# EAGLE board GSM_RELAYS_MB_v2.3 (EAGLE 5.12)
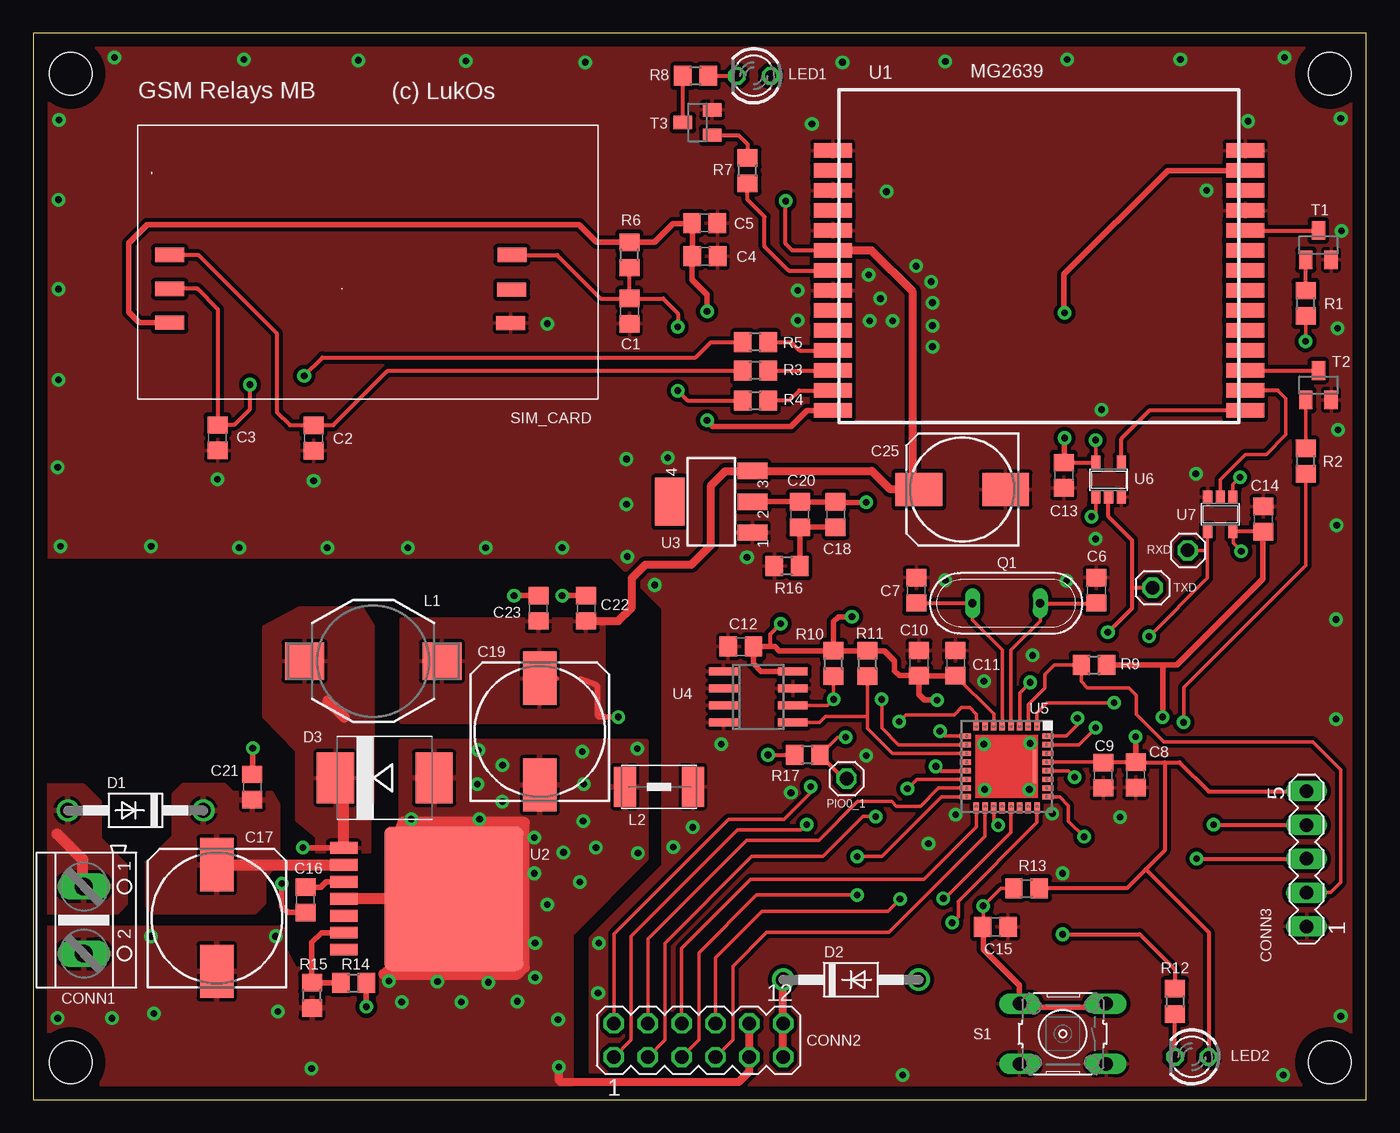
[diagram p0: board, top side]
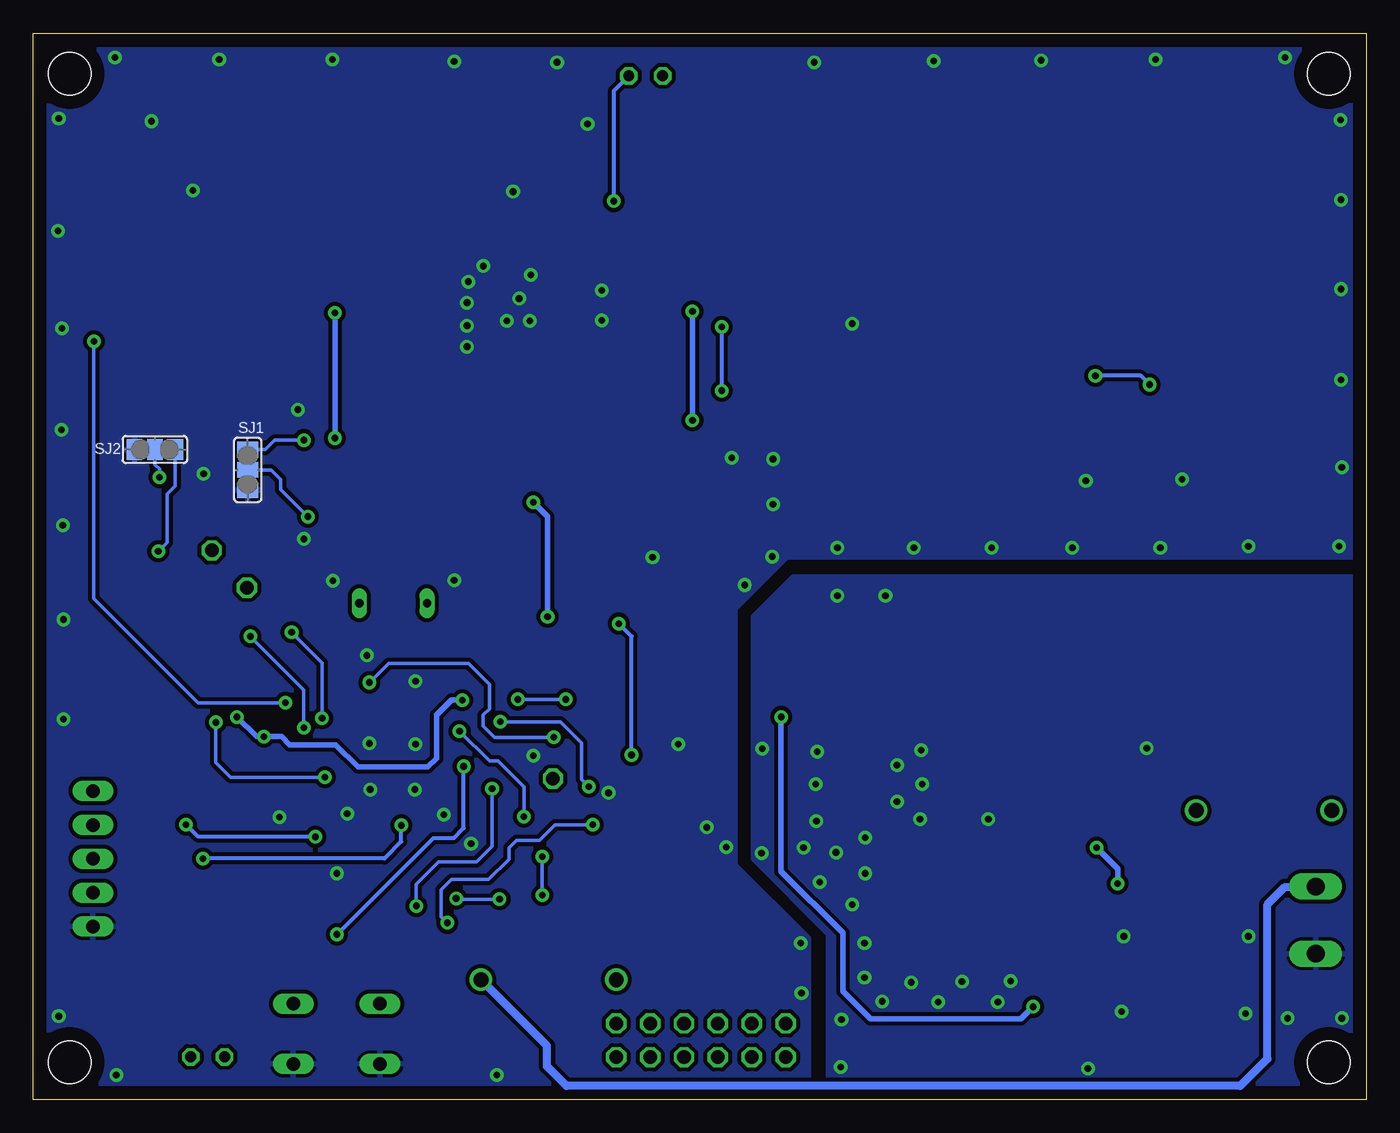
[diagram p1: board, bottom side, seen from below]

Size 100 x 80 mm. Coordinates in mm from the lower left corner, seen from the top.
Outline: 0,0 100,0 100,80 0,80 0,0
Copper layers (1*16): Top 0.035mm / dielectric 1.5mm / Bottom 0.035mm
Design rules "default": minimum track width 10mil, minimum drill 24mil, track to track 8mil, track to pad 8mil, pad to pad 8mil, via to via 8mil, smd to smd 8mil, copper to edge 40mil, drill to drill 8mil, minimum pad ring 10mil, minimum via ring 8mil, stop-mask expansion 4mil, vias tented up to drill 0mil, thermal gap 10mil
Holes 3.2 mm at 2.79,2.79 2.79,76.96 97.28,2.79 97.28,76.96
tRestrict: area 51.4,31.3 to 52.3,31.6; area 51.3,30.1 to 52.2,30.3; area 51.3,28.8 to 52.2,29.1

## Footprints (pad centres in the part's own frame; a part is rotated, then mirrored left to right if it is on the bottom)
C0805 = smd 1.3 x 1.5: 1 -0.95,0; 2 0.95,0
153CLV-1010 = smd 4 x 2.5: + 4,0; - -4,0
153CLV-0810 = smd 3.5 x 2.5: + 3.25,0; - -3.25,0
AK500/2 = drill 1.321 long: 1 -2.515,0; 2 2.515,0
MA06-2 = drill 1.016 octagon: 1 -6.35,-1.27; 2 -6.35,1.27; 3 -3.81,-1.27; 4 -3.81,1.27; 5 -1.27,-1.27; 6 -1.27,1.27; 7 1.27,-1.27; 8 1.27,1.27; 9 3.81,-1.27; 10 3.81,1.27; 11 6.35,-1.27; 12 6.35,1.27
MA05-1 = drill 1.016 long: 1 -5.08,0; 2 -2.54,0; 3 0,0; 4 2.54,0; 5 5.08,0
DO41-10 = drill 1.118 round: A 5.08,0; C -5.08,0
SMC = smd 2.8 x 3.8: A 3.7,0; C -3.7,0
P0762NL = smd 2.794 x 2.921: 1 0,5.156; 2 0,-5.156
1812 = smd 1.65 x 3: 1 -2.55,0; 2 2.55,0
LED3MM = drill 0.813 octagon: A -1.27,0; K 1.27,0
1X01 = drill 1.016 octagon: 1 0,0
QS = drill 0.61 long: 1 -2.54,0; 2 2.54,0
R0805 = smd 1.3 x 1.5: 1 -0.95,0; 2 0.95,0
B3F-10XX = drill 1.016 long: 1 -3.251,2.261; 2 3.251,2.261; 3 -3.251,-2.261; 4 3.251,-2.261
UICC_READER_I = smd 2.184 x 1.067: C1 12.88,2.54; C2 12.88,0; C3 12.88,-2.54; C5 -12.7,2.58; C6 -12.78,0.06; C7 -12.8,-2.54
SJ_2 = smd 1.168 x 1.6: 1 -1.524,0; 2 0,0; 3 1.524,0
SOT23 = smd 1 x 1.4: 1 -0.95,-1.1; 2 0.95,-1.1; 3 0,1.1
F_MG2639 = smd 1.1 x 2.85: 1 -8.724,-16.361; 2 -7.224,-16.361; 3 -5.724,-16.361; 4 -4.224,-16.361; 5 -2.724,-16.361; 6 -1.224,-16.361; 7 0.276,-16.361; 8 1.776,-16.361; 9 3.276,-16.361; 10 4.776,-16.361; 11 6.276,-16.361; 12 7.776,-16.361; 13 9.276,-16.361; 14 10.776,-16.361; 15 10.776,14.561; 16 9.276,14.561; 17 7.776,14.561; 18 6.276,14.561; 19 4.776,14.561; 20 3.276,14.561; 21 1.776,14.561; 22 0.276,14.561; 23 -1.224,14.561; 24 -2.724,14.561; 25 -4.224,14.561; 26 -5.724,14.561; 27 -7.224,14.561; 28 -8.724,14.561
TO263-7 = smd 0.91 x 2.16: 1 -3.81,-8.255; 2 -2.54,-8.255; 3 -1.27,-8.255; 4 0,-8.255; 5 1.27,-8.255; 6 2.54,-8.255; 7 3.81,-8.255 | smd 10.8 x 10.41: P$8 0,0
SOT223 = smd 1.219 x 2.235: 1 -2.311,-3.099; 2 0,-3.099; 3 2.311,-3.099 | smd 3.6 x 2.2: 4 0,3.099
SO-08 = smd 0.6 x 2.2: 1 -1.905,-2.6; 2 -0.635,-2.6; 3 0.635,-2.6; 4 1.905,-2.6; 5 1.905,2.6; 6 0.635,2.6; 7 -0.635,2.6; 8 -1.905,2.6
HVQFN33-7X7 = smd 0.813 x 0.406: 1 -3.1,2.275; 2 -3.1,1.625; 3 -3.1,0.975; 4 -3.1,0.325; 5 -3.1,-0.325; 6 -3.1,-0.975; 7 -3.1,-1.625; 8 -3.1,-2.275; 17 3.1,-2.275; 18 3.1,-1.625; 19 3.1,-0.975; 20 3.1,-0.325; 21 3.1,0.325; 22 3.1,0.975; 23 3.1,1.625; 24 3.1,2.275 | smd 0.406 x 0.813: 9 -2.275,-3.1; 10 -1.625,-3.1; 11 -0.975,-3.1; 12 -0.325,-3.1; 13 0.325,-3.1; 14 0.975,-3.1; 15 1.625,-3.1; 16 2.275,-3.1; 25 2.275,3.1; 26 1.625,3.1; 27 0.975,3.1; 28 0.325,3.1; 29 -0.325,3.1; 30 -0.975,3.1; 31 -1.625,3.1; 32 -2.275,3.1 | smd 2.54 x 0.254: 33 0,2.1
SOT23-5 = smd 0.69 x 0.99: 1 -0.95,-1.29; 2 0,-1.29; 3 0.95,-1.29; 4 0.95,1.3; 5 -0.95,1.3

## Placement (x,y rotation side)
C1  12p  [C0805]  44.73,59.16 270 top
C2  12p  [C0805]  21.03,49.63 270 top
C3  12p  [C0805]  13.82,49.66 270 top
C4  10u  [C0805]  50.39,63.27 0 top
C5  33p  [C0805]  50.37,65.76 0 top
C6  18p  [C0805]  79.76,38.2 90 top
C7  18p  [C0805]  66.24,38.2 90 top
C8  10u  [C0805]  82.7,24.36 270 top
C9  100n  [C0805]  80.26,24.33 270 top
C10  10u  [C0805]  66.45,32.74 90 top
C11  100n  [C0805]  69.19,32.74 90 top
C12  100n  [C0805]  53.09,33.99 0 top
C13  100n  [C0805]  77.32,46.84 270 top
C14  100n  [C0805]  92.28,43.56 90 top
C15  100n  [C0805]  72.19,12.95 180 top
C16  10n  [C0805]  20.42,14.99 270 top
C17  470u  [153CLV-1010]  13.77,13.61 90 top
C18  4.7u  [C0805]  60.2,43.89 270 top
C19  560u  [153CLV-1010]  38,27.61 90 top
C20  4.7u  [C0805]  57.51,43.89 270 top
C21  100n  [C0805]  16.43,23.44 270 top
C22  100n  [C0805]  41.48,36.86 270 top
C23  1n  [C0805]  37.9,36.86 270 top
C25  330u  [153CLV-0810]  69.7,45.77 180 top
CONN1  [AK500/2]  3.78,13.46 270 top
CONN2  [MA06-2]  49.91,4.45 0 top
CONN3  [MA05-1]  95.53,18.06 90 top
D1  1N4004  [DO41-10]  7.67,21.69 180 top
D2  1N4004  [DO41-10]  61.34,8.99 0 top
D3  MBRS340  [SMC]  26.37,24.13 0 top
L1  22uH/2.7A  [P0762NL]  25.5,32.89 90 top
L2  60R/3A  [1812]  46.94,23.47 0 top
LED1  [LED3MM]  54.05,76.81 180 top
LED2  [LED3MM]  86.92,3.2 180 top
PIO0_1  [1X01]  61.01,24.08 0 top
Q1  12MHz  [QS]  73,37.24 180 top
R1  4k7  [R0805]  95.45,59.74 90 top
R2  4k7  [R0805]  95.45,47.9 90 top
R3  33  [R0805]  54.18,52.45 0 top
R4  33  [R0805]  54.18,54.69 180 top
R5  33  [R0805]  54.18,56.82 180 top
R6  10k  [R0805]  44.73,63.37 90 top
R7  4k7  [R0805]  53.59,69.7 90 top
R8  330  [R0805]  49.68,76.81 0 top
R9  10k  [R0805]  79.58,32.61 0 top
R10  4k7  [R0805]  60.05,32.72 90 top
R11  4k7  [R0805]  62.59,32.72 90 top
R12  330  [R0805]  85.65,7.37 270 top
R13  4k7  [R0805]  74.52,15.85 0 top
R14  2k2/1%  [R0805]  24.03,8.76 0 top
R15  1k/1%  [R0805]  20.9,7.82 90 top
R16  5.1  [R0805]  56.54,40.03 180 top
R17  10k  [R0805]  58.06,25.86 180 top
RXD  [1X01]  86.61,41.2 0 top
S1  [B3F-10XX]  77.24,4.93 180 top
SIM_CARD  UICC_TYPE1  [UICC_READER_I]  23.11,60.83 180 top
SJ1  [SJ_2]  83.92,47.24 270 bottom
SJ2  [SJ_2]  90.88,48.77 180 bottom
T1  BC846  [SOT23]  96.42,64.11 0 top
T2  BC846  [SOT23]  96.42,53.59 0 top
T3  BC846  [SOT23]  49.83,73.3 90 top
TXD  [1X01]  83.97,38.4 0 top
U1  MG2639  [F_MG2639]  76.35,62.48 270 top
U2  LM2676  [TO263-7]  31.55,15.06 270 top
U3  TC2117  [SOT223]  50.85,44.86 90 top
U4  24LC04  [SO-08]  54.38,30.2 270 top
U5  LPC1114FHN33  [HVQFN33-7X7]  73.03,24.99 270 top
U6  74LVC1G125  [SOT23-5]  80.67,46.51 0 top
U7  74LVC1G125  [SOT23-5]  89.05,43.92 180 top

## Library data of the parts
C1-C23 C25 Q1 R1-R17 T1-T3 = Luk_lib
CONN1 = con-ptr500; OC_FARNELL: unknown; OC_NEWARK: unknown
CONN2 CONN3 = con-lstb; OC_FARNELL: unknown; OC_NEWARK: unknown
D1-D3 = diode
L1 = inductors
L2 = wuerth_elektronik_eisos__v6.0
LED1 LED2 = led
PIO0_1 RXD TXD = pinhead
S1 = switch-omron; MPN: B3F-1000; OC_FARNELL: 176432; OC_NEWARK: 36M3542
SIM_CARD = uicc_card_reader
SJ1 SJ2 = jumper
U1 = GSM_ZTE_MG2639_v2
U2 = national-semiconductor
U3 = v-reg-3
U4 = microchip-6a
U5 = lpc1xxx-v6
U6 U7 = 74xx-little-us

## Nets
+3V3: C8.1 C9.1 C10.1 C11.1 C12.2 C14.1 C18.1 C20.1 CONN3.5 LED2.A R9.2 R10.2 R11.2 R13.2 R17.2 SJ2.1 U3.2 U4.8 U5.6 U5.29 U7.5
+12V: CONN2.11 CONN2.12 D2.C
AGND: C17.- C19.- C21.1 C22.1 C23.1 CONN1.2 CONN2.9 CONN2.10 D3.A L2.1 R15.1 U2.4
CARD_CLK: R4.1 U1.12
CARD_DATA: R3.2 U1.13
CARD_RST: R5.1 U1.11
GND: C1.2 C2.2 C3.2 C4.2 C5.2 C6.2 C7.2 C8.2 C9.2 C10.2 C11.2 C12.1 C13.2 C14.2 C15.1 C25.- CONN3.1 L2.2 R16.2 S1.1 S1.2 SIM_CARD.C5 SJ1.3 SJ2.3 T1.2 T2.2 T3.2 U1.1 U1.3 U1.5 U1.8 U1.25 U1.28 U3.1 U4.1 U4.2 U4.3 U4.4 U4.7 U5.33 U6.3 U7.3
GSM_R: R2.1 U5.28
LED: R12.1 U5.13
M_RXD: RXD.1 U5.31 U7.4
M_TXD: TXD.1 U5.32 U6.2
N$1: R1.2 T1.1
N$2: R2.2 T2.1
N$3: C1.1 R3.1 R6.1 SIM_CARD.C7
N$4: R8.1 T3.3
N$5: C2.1 R4.2 SIM_CARD.C3
N$6: C3.1 R5.2 SIM_CARD.C2
N$7: R7.2 T3.1
N$8: LED2.K R12.2
N$9: LED1.K R8.2
N$10: R14.1 R15.2 U2.6
N$11: C16.1 U2.3
N$12: C16.2 D3.C L1.1 U2.1
N$13: SJ1.2 U6.1
N$14: C17.+ C21.2 D1.C U2.2
N$15: SJ2.2 U7.1
N$16: CONN1.1 D1.A D2.A
N$17: C18.2 C20.2 R16.1
N$18: PIO0_1.1 R17.1 U5.3
ON_OFF: R1.1 U5.1
PK1: CONN2.1 U5.24
PK2: CONN2.2 U5.8
PK3: CONN2.3 U5.9
PK4: CONN2.4 U5.15
PK5: CONN2.5 U5.16
PK6: CONN2.6 U5.17
PK7: CONN2.7 U5.18
PK8: CONN2.8 U5.21
PWRKEY_N: T1.3 U1.24
RESET: CONN3.2 R9.1 U5.2
RSSI_LED: R7.1 U1.7
RXD: U1.15 U6.4
SCL: R10.1 U4.6 U5.10
SDA: R11.1 U4.5 U5.11
SW1: C15.2 R13.1 S1.3 S1.4 U5.14
SWCLK: CONN3.3 U5.19
SWDIO: CONN3.4 U5.25
SYSRST_N: T2.3 U1.17
TXD: U1.16 U7.2
V_CARD: C4.1 C5.1 R6.2 SIM_CARD.C1 U1.14
V_MSM: C13.1 SJ1.1 U1.27 U6.5
VBAT: C19.+ C22.2 C23.2 C25.+ L1.2 LED1.A R14.2 U1.6 U3.3
XTALIN: C6.1 Q1.1 U5.4
XTALOUT: C7.1 Q1.2 U5.5

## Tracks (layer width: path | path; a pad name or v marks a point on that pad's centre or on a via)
+3V3  (via drill 0.5 pad 1.02)
  Top 0.254: C11.1 72.05,28.93 U5.6 | U5.29 80.23,25.32 C9.1 | v90.63,41.15 90.02,41.76 90.02,42.6 U7.5
  Top 0.305: C9.1 82.68,25.28 C8.1 84.89,25.31 | 84.89,25.31 85.99,25.31 88.19,23.11 95.5,23.11 CONN3.5 | R13.2 82.04,15.85 83.46,17.27 | 83.46,17.27 84.89,18.69 84.89,25.31 | C14.1 U7.5 | LED2.A 88.19,12.55 83.46,17.27 | v55.12,25.86 R17.2 | v56.08,35.71 55.27,34.9 55.27,33.98
  Top 0.406: R10.2 R11.2 63.87,33.66 64.62,32.92 64.62,32.16 64.97,31.8 66.44,31.8 C10.1 | C10.1 C11.1 | v84.73,28.7 84.73,32.61 | 84.73,32.61 R9.2 | 84.73,32.61 85.8,32.61 92.25,39.06 92.25,42.59 C14.1 | v67.82,29.97 66.85,29.97 66.45,30.38 C10.1 | v82.7,27.23 C8.1 | U4.8 54.61,32.11 54.05,32.66 54.04,32.66 C12.2 | U3.2 57.49,44.86 C20.1 C18.1 60.23,44.81 v62.48,44.81 | C12.2 54.09,33.93 | R10.2 55.95,33.66 55.63,33.98 55.27,33.98 C12.2 | v61.42,36.22 60.4,36.22 60.05,35.87 R10.2
  Bottom 0.254: SJ2.1 89.36,46.02 89.97,45.41 89.97,41.81 v90.63,41.15
  Bottom 0.305: v55.12,25.86 55.12,34.75 v56.08,35.71
  Bottom 0.406: v84.73,28.7 83.26,27.23 v82.7,27.23 | v82.7,27.23 81.67,27.23 | v82.7,27.23 81.38,27.23 80.77,26.62 77.32,26.62 75.64,24.94 70.41,24.94 69.75,25.6 69.75,28.85 68.63,29.97 v67.82,29.97 | v61.42,36.22 61.42,43.74 v62.48,44.81
+12V
  Top 0.61: 56.29,3.15 CONN2.11 CONN2.12 D2.C
AGND  (via drill 0.5 pad 1.02)
  Top 0.406: C21.1 16.46,24.39 v16.46,26.36 | C23.1 36.12,37.8 v36.07,37.8 | C22.1 39.69,37.8 v39.67,37.8 | v26.67,8.89 26.72,9.4
  Top 0.61: CONN2.10 CONN2.9 53.72,2.11 52.93,1.32 39.57,1.32 39.42,1.47 v39.42,2.44
  Top 0.813: U2.4 26.64,15.06 26.67,15.04 27.03,15.04 | 27.03,15.04 27.08,15.04 27.08,19.3 27.74,20.83 36.83,20.78 36.83,9.91 36.32,9.4 26.72,9.4 26.31,9.4 26.98,9.91 26.98,14.99 27.03,15.04
  Bottom 0.406: v39.67,37.8 39.62,37.8
  other vias: 1.83,6.1 5.89,6.1 9.04,6.45 18.19,12.24 8.84,12.24 18.34,6.6 20.88,2.34 41.2,26.11 41.25,20.88 41,16.31 38.56,14.63 37.64,9.14 36.32,7.37 27.64,7.32 33.32,23.67 33.38,26.21 28.35,21.03 33.48,21.03 37.59,19.66 37.59,16.97 37.64,11.73 39.78,18.54 34.14,8.79 30.33,8.84 32.11,7.32 39.37,5.99 35.2,25.1 35.2,22.35 45.31,26.31 45.36,18.49 41.3,23.67 42.21,18.9
  pour Top (isolate 0.305): 0.25,12.85 18.54,12.85 18.85,12.65 18.85,11.23 19.66,9.75 25.7,9.75 26.52,10.57 26.72,20.22 27.58,20.22 27.58,26.87 45.97,26.87 45.97,18.08 40.34,12.45 40.34,0.41 20.12,0.3 0.25,0.3
  pour Bottom (isolate 0.305): 42.98,39.22 0.51,39.22 0.41,0.51 12.24,0.46 12.7,0.41 40.34,0.46 40.34,12.45 45.97,18.08 45.97,36.22
  pour Top (isolate 0.254): 43.48,26.87 43.43,26.87 43.43,26.82
CARD_CLK
  Top 0.305: R4.1 55.15,54.71 U1.12
CARD_DATA
  Top 0.305: R3.2 55.15,52.48 56.74,52.48 57.48,53.21 U1.13
CARD_RST
  Top 0.305: R5.1 55.15,56.84 56.84,56.84 57.48,56.21 U1.11
GND  (via drill 0.5 pad 1.02)
  Top 0.254: U5.33 75.12,26.37 v74.78,26.72
  other vias: 71.37,23.27 71.32,26.67 74.73,23.27 62.48,25.81 56.85,23.01 51.61,26.67 46.63,38.61 44.55,40.74 21.03,46.43 13.82,46.53 2.03,41.5 1.93,73.51 6.1,78.18 93.88,78.18 98.09,73.61 98.09,6.25 93.78,1.83 76.45,21.44 67.16,19.2 69.19,21.39 53.54,40.69 62.69,61.87 38.56,58.22 44.5,48.06 49.48,20.42 65.23,1.83 97.74,28.55 97.79,43.08 97.84,57.86 24.38,77.98 60.71,77.83 77.57,78.03 88.04,68.22 80.16,51.77 64.01,68.12 44.5,44.65 81.53,21.18 68.43,38.96 77.52,38.91 47.6,48.16 15.8,78.03 32.46,77.93 1.88,67.51 1.88,60.81 1.88,54 1.83,47.45 8.84,41.5 15.44,41.4 22.05,41.4 28.09,41.4 33.93,41.4 39.67,41.4 42.37,7.98 42.42,11.73 48.01,18.95 97.74,36.02 86.06,78.03 68.43,77.88 41.4,77.83 98.15,65.18 97.89,50.24 62.74,58.42 63.55,60.1 66.24,62.53 67.36,61.37 67.46,59.79 67.46,58.06 67.46,56.49 58.42,73.2 57.35,60.71 91.14,73.41 77.22,16.97 64.47,58.42 71.32,31.39 74.98,33.32 57.35,58.47 79.71,42.06 87.22,46.94
  pour Bottom (isolate 0.305): 0.51,79.45 99.47,79.45 99.47,0.51 41.86,0.51 41.86,11.99 41.86,12.09 47.35,17.58 47.35,36.83 43.48,40.69 0.51,40.69
  pour Top (isolate 0.305): 0.76,79.5 99.67,79.5 99.67,0.61 41.81,0.61 41.81,12.09 41.81,12.14 47.24,17.58 47.24,36.83 43.38,40.69 0.76,40.69
GSM_R  (via drill 0.5 pad 1.02)
  Top 0.254: R2.1 95.45,40.08 86.31,30.94 v86.31,28.3 | U5.28 77.64,24.67 v78.13,24.18
  Bottom 0.254: v78.13,24.18 85.19,24.18 86.31,25.3 v86.31,28.3
LED  (via drill 0.5 pad 1.02)
  Top 0.305: U5.13 68.04,24.67 v67.72,24.99 | v77.22,12.39 83.01,12.39 85.65,9.75 R12.1
  Bottom 0.305: v67.72,24.99 67.72,20.37 68.48,19.61 70,19.61 v77.22,12.39
M_RXD  (via drill 0.5 pad 1.02)
  Top 0.254: U5.31 78.44,26.62 v79.7,27.89 | U7.4 88.09,42.6 88.09,41.2 | v83.72,34.75 88.09,39.12 88.09,41.2 | 88.09,41.2 RXD.1
  Bottom 0.254: v79.7,27.89 79.7,30.73 v83.72,34.75
M_TXD  (via drill 0.5 pad 1.02)
  Top 0.254: U5.32 77.51,27.27 78.33,28.09 v78.33,28.6 | v80.62,35.05 80.67,35.1
  Top 0.305: U6.2 80.67,43.74 82.45,41.96 82.45,38.41 | 82.45,38.41 82.45,36.88 v80.62,35.05 | 82.45,38.41 TXD.1
  Bottom 0.254: v78.33,28.6 78.33,32.77 v80.62,35.05
N$1
  Top 0.305: T1.1 95.47,60.71 R1.2
N$2
  Top 0.254: T2.1 95.47,48.87 R2.2
N$3  (via drill 0.5 pad 1.02)
  Top 0.305: SIM_CARD.C7 39.29,63.37 42.56,60.11 C1.1 | 44.72,62.43 R6.1 C1.1 | R3.1 49.1,52.45 v48.36,53.19 | v48.36,57.96 48.36,58.98 47.24,60.1 44.74,60.1 C1.1
  Bottom 0.305: v48.36,57.96 v48.36,53.19
N$4
  Top 0.305: R8.1 T3.3
N$5
  Top 0.305: SIM_CARD.C3 10.26,63.35 12.39,63.35 18.29,57.45 18.29,51.56 19.25,50.6 21.05,50.6 | R4.2 26.59,54.69 22.5,50.6 21.05,50.6 | 21.05,50.6 C2.1
N$6  (via drill 0.5 pad 1.02)
  Top 0.305: R5.2 50.83,56.82 49.68,55.68 21.69,55.68 v20.32,54.3 | v16.26,53.65 16.26,51.82 15.09,50.65 13.86,50.65 C3.1 13.87,50.66 13.87,59.28 12.32,60.83 SIM_CARD.C2
  Bottom 0.305: v20.32,54.3 16.92,54.3 v16.26,53.65
N$7
  Top 0.305: T3.1 52.92,72.35 53.59,71.68 R7.2
N$8
  Top 0.305: LED2.K R12.2
N$9
  Top 0.305: R8.2 LED1.K
N$10
  Top 0.406: U2.6 21.61,12.52 20.88,11.79 20.88,8.8 R15.2 23.07,8.77 R14.1
N$11
  Top 0.406: U2.3 21.97,16.33 21.54,15.9 20.46,15.9 C16.1
N$12  (via drill 0.5 pad 1.02)
  Top 0.406: C16.2 19.09,14.04 18.64,14.48 v18.64,16.2 | v20.22,18.9 23.27,18.9 U2.1
  Top 0.813: U2.1 23.29,24.66 D3.C | 22.1,29.92 23.33,28.69
  Bottom 0.406: v18.64,16.2 18.64,17.32 v20.22,18.9
  pour Top (isolate 0.305): 21.29,18.59 21.29,19.71 19.81,20.93 19.81,26.16 17.32,28.7 17.32,35.46 19.96,36.88 24.64,36.88 25.45,35.56 25.45,22.4 25.2,21.23 25.2,18.59
N$13  (via drill 0.5 pad 1.02)
  Top 0.254: U6.1 79.72,44.06 v79.4,43.74
  Bottom 0.254: v79.4,43.74 81.43,45.77 81.43,46.53 82.14,47.24 SJ1.2
N$14
  Top 0.813: U2.2 14.74,17.6 C17.+
  pour Top: 16.56,14.07 9.04,14.07 8.59,14.53 8.59,17.68 10.57,19.66 10.57,22.86 11.28,23.57 14.27,23.57 14.88,22.96 17.83,22.96 18.34,22.15 18.34,17.98 17.27,16.61 17.27,14.78
N$15  (via drill 0.5 pad 1.02)
  Top 0.254: U7.1 90,46.16 v90.53,46.69
  Bottom 0.254: v90.53,46.69 90.53,47.3 90.88,47.65 SJ2.2
N$16
  Top 0.813: 1.78,19.91 3.71,17.98 3.71,16 CONN1.1
  Bottom 0.61: D2.A 61.47,4.04 61.47,2.49 59.99,1.02 9.45,1.02 7.42,3.05 7.42,14.63 6.1,15.95 3.81,15.95 CONN1.1
  pour Top (isolate 0.305): 0.25,23.52 3.71,23.52 4.93,22.3 4.93,19.51 6.91,17.53 6.91,14.73 6.3,14.07 1.12,14.07 0.25,14.83 0.2,23.47
N$17
  Top 0.406: R16.1 57.51,40.05 C20.2 C18.2
N$18  (via drill 0.5 pad 1.02)
  Top 0.254: U5.3 74,30.52 v74.78,31.29 | v60.96,27.18 60.34,27.18 R17.1
  Top 0.305: PIO0_1.1 60.79,24.08 R17.1
  Bottom 0.254: v74.78,31.29 73.36,32.72 67.36,32.72 65.79,31.14 65.79,29.31 66.24,28.85 66.24,28.04 65.38,27.18 v60.96,27.18
ON_OFF  (via drill 0.5 pad 1.02)
  Top 0.254: U5.1 75.3,29.02 76.05,29.77 v81.08,29.77 | v95.45,56.9 R1.1
  Bottom 0.254: v95.45,56.9 95.45,45.01 95.45,44.65 95.45,37.59 87.63,29.77 v81.08,29.77
PK1  (via drill 0.5 pad 1.02)
  Top 0.254: CONN2.1 44.86,4.47 44.86,12.24 52.83,20.22 57.61,20.22 v58.01,20.62 | U5.24 75.3,20.79 69.39,14.88 69.39,13.72 v68.94,13.26
  Bottom 0.254: v68.94,13.26 69.39,13.72 69.39,15.75 68.63,16.51 65.84,16.51 64.31,18.03 64.31,18.9 63.75,19.46 62.03,19.46 60.86,20.62 v58.01,20.62
PK2  (via drill 0.5 pad 1.02)
  Top 0.254: v58.32,23.47 58.32,23.01 56.34,21.03 52.17,21.03 43.56,12.42 CONN2.2 | U5.8 70.76,28.11 70.76,28.91 70.26,29.41 69.65,29.41 69.09,28.85 65.48,28.85 v64.97,28.35
  Bottom 0.254: v64.97,28.35 60.45,28.35 58.88,26.77 58.88,24.03 v58.32,23.47
PK3  (via drill 0.5 pad 1.02)
  Top 0.254: CONN2.3 47.4,4.47 47.4,11.73 53.9,18.24 59.23,18.24 62.23,21.23 v63.2,21.23 | U5.9 68.39,27.27 v68.02,27.64
  Bottom 0.254: v63.2,21.23 63.2,23.47 65.13,25.4 65.79,25.4 v68.02,27.64
PK4
  Top 0.254: U5.15 67.92,23.37 66.55,22 64.77,22 64.41,22.35 61.82,22.35 58.93,19.46 53.49,19.46 46.1,12.06 CONN2.4
PK5  (via drill 0.5 pad 1.02)
  Top 0.254: CONN2.5 49.94,4.47 49.94,11.02 54.25,15.34 v61.82,15.34 | U5.16 68.13,22.72 63.65,18.24 v61.82,18.24
  Bottom 0.254: v61.82,15.34 v61.82,18.24
PK6
  Top 0.254: U5.17 70.75,20.46 66.8,16.51 53.8,16.51 48.64,11.35 CONN2.6
PK7
  Top 0.254: U5.18 71.4,19.74 64.21,12.55 55.02,12.55 52.48,10.01 52.48,4.47 CONN2.7
PK8  (via drill 0.5 pad 1.02)
  Top 0.254: U5.21 73.35,20.06 68.38,15.09 v68.28,15.09 | CONN2.8 51.18,10.64 54.66,14.12 64.11,14.12 v65.02,15.04
  Bottom 0.254: v65.02,15.04 68.22,15.04 v68.28,15.09
PWRKEY_N
  Top 0.305: T1.3 U1.24
RESET
  Top 0.254: U5.2 74.65,29.64 75.89,30.89 75.89,31.9 76.61,32.61 R9.1 78.63,31.35 79.1,30.89 82.19,30.89 82.75,30.33 82.75,28.91 84.84,26.82 96.01,26.82 98.09,24.74 98.09,16.31 97.33,15.54 95.56,15.54 CONN3.2
RSSI_LED
  Top 0.305: R7.1 53.59,67.51 54.86,66.24 54.86,64.01 56.66,62.21 U1.7
RXD
  Top 0.254: U6.4 81.64,47.82
  Top 0.305: 81.64,47.82 81.64,49.58 83.77,51.71 U1.15
SCL  (via drill 0.5 pad 1.02)
  Top 0.254: 60.03,31.75 R10.1 v60.05,30.02 59.59,29.57 U4.6 | U5.10 64.92,26.62 63.65,27.89 v63.65,30.02
  Bottom 0.254: v60.05,30.02 v63.65,30.02
SDA
  Top 0.254: U5.11 64.45,25.97 62.59,27.84 62.59,28.75 | 62.59,28.75 R11.1 | 62.59,28.75 59.44,28.75 58.98,28.3 U4.5
SW1  (via drill 0.5 pad 1.02)
  Top 0.254: U5.14 66.28,24.02 v65.58,23.32 | 71.27,12.99 v71.27,14.53 72.59,15.85 R13.1
  Top 0.305: C15.2 71.27,12.99
  Top 0.406: S1.3 80.47,6.91 74.02,6.91 74.02,7.16 S1.4 73.97,7.21 73.97,8.59 71.27,11.28 71.27,12.92 C15.2
  Bottom 0.254: v65.58,23.32 65.58,19 66.75,17.83 69.6,17.83 71.27,16.15 v71.27,14.53
SWCLK  (via drill 0.5 pad 1.02)
  Top 0.254: U5.19 72.05,20.91 v72.39,20.57
  Top 0.305: CONN3.3 87.3,18.06 v87.27,18.09
  Bottom 0.305: v72.39,20.57 72.39,19.36 73.66,18.09 v87.27,18.09
SWDIO  (via drill 0.5 pad 1.02)
  Top 0.254: U5.25 77,22.72 77.67,22.05 77.67,20.88 v78.84,19.71 | 95.5,20.62 CONN3.4
  Top 0.305: v88.54,20.62 95.5,20.62
  Bottom 0.305: v78.84,19.71 87.63,19.71 v88.54,20.62
SYSRST_N
  Top 0.305: T2.3 96.41,54.71 U1.17
TXD
  Top 0.254: 93.35,53.21 93.98,52.58 93.98,49.89 92.51,48.41 90.93,48.41 89.05,46.53 U7.2
  Top 0.305: 93.35,53.21 U1.16
V_CARD  (via drill 0.5 pad 1.02)
  Top 0.406: SIM_CARD.C1 7.95,58.29 7.16,59.08 7.16,64.26 8.53,65.63 40.95,65.63 42.27,64.31 R6.2 46.59,64.32 48.01,65.73 49.39,65.73 C5.1 49.44,65.73 C4.1 49.43,63.26 49.43,61.52 50.55,60.4 v50.55,59.13 | v50.55,50.95 51,50.49 56.84,50.49 58.06,51.71 U1.14
  Bottom 0.406: v50.55,59.13 v50.55,50.95
V_MSM  (via drill 0.5 pad 1.02)
  Top 0.254: U6.5 79.72,49.46 v79.7,49.48
  Top 0.305: C13.1 79.7,47.79 U6.5
  Top 0.406: v77.37,59.03 77.32,59.08 77.32,61.92 85.1,69.71 U1.27 | v77.37,49.63 77.37,47.84 C13.1
  Bottom 0.254: v79.7,49.48 81.89,49.48 82.6,48.77 SJ1.1
  Bottom 0.406: v77.37,49.63 v77.37,59.03
VBAT  (via drill 0.5 pad 1.02)
  Top 0.305: v56.44,67.41 56.44,64.21 56.94,63.71 U1.6 60.23,63.7
  Top 0.406: 37.24,31.14 39.2,31.6 | 53.92,47.14 U3.3 | R14.2 24.98,6.97 v24.99,6.96 | v43.89,28.7 42.42,28.7 42.32,28.8 42.32,30.99 42.16,31.14 41.06,31.55
  Top 0.61: C22.2 43.88,35.91 44.91,36.93 44.91,39.12 45.92,40.13 49.38,40.13 50.85,41.6 50.85,46.08 51.92,47.14 53.92,47.14 | 60.23,63.7 62.89,63.7 65.99,60.6 65.99,46.03 C25.+ | C25.+ 66.09,45.92 | U3.3 62.92,47.17 64.26,45.82 66.4,45.82 C25.+
  Bottom 0.305: v56.44,67.41 56.44,75.69 LED1.A
  Bottom 0.406: v24.99,6.96 25.91,6.04 37.19,6.04 39.27,8.13 39.27,12.5 43.89,17.12 v43.89,28.7
  pour Top (isolate 0.305): 27.58,36.02 27.58,28.35 42.82,28.35 42.82,36.02
XTALIN
  Top 0.254: U5.4 73.35,33.73 75.54,35.92 Q1.1
  Top 0.305: Q1.1 79.74,37.24 C6.1
XTALOUT
  Top 0.254: U5.5 72.7,33.73 70.46,35.97 Q1.2
  Top 0.305: Q1.2 66.31,37.24 C7.1

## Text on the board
bOrigins: 1 | 2 | 3 | 1 | 2 | 3
tNames: GSM Relays MB | (c) LukOs
tDocu: +3V3 | SWDIO | SWCLK | RESET | GND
